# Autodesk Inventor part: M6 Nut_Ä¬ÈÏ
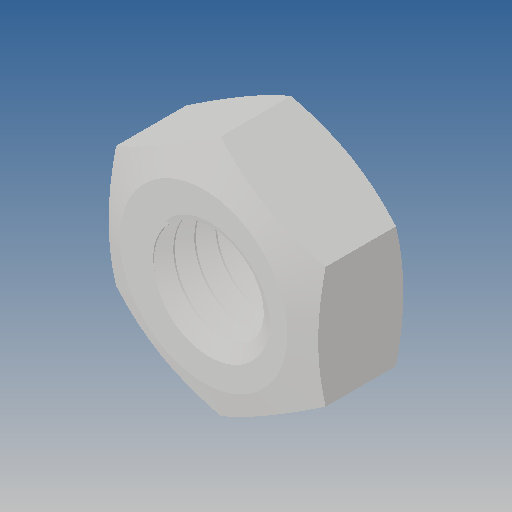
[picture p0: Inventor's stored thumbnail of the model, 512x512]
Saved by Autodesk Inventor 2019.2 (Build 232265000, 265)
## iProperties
Created: 2010-06
Part Number: M6 Nut_Ä¬ÈÏ
Material: Ogólny
Document SubType Name: Modeling
Designer: CADENGINEERING4
Density: 1 g/cm^3
Appearance: Domyślna
Author: CADENGINEERING4
Revision Number: ÈÎºÎ
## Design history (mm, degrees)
feature "NONE"
node "Bryła1"
